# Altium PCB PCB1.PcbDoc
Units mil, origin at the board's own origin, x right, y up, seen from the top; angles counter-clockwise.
Board outline 6000 x 4000 mil, 2 copper layers (Top Layer, Bottom Layer); 0 components, 0 nets, 0 pads, 0 vias.
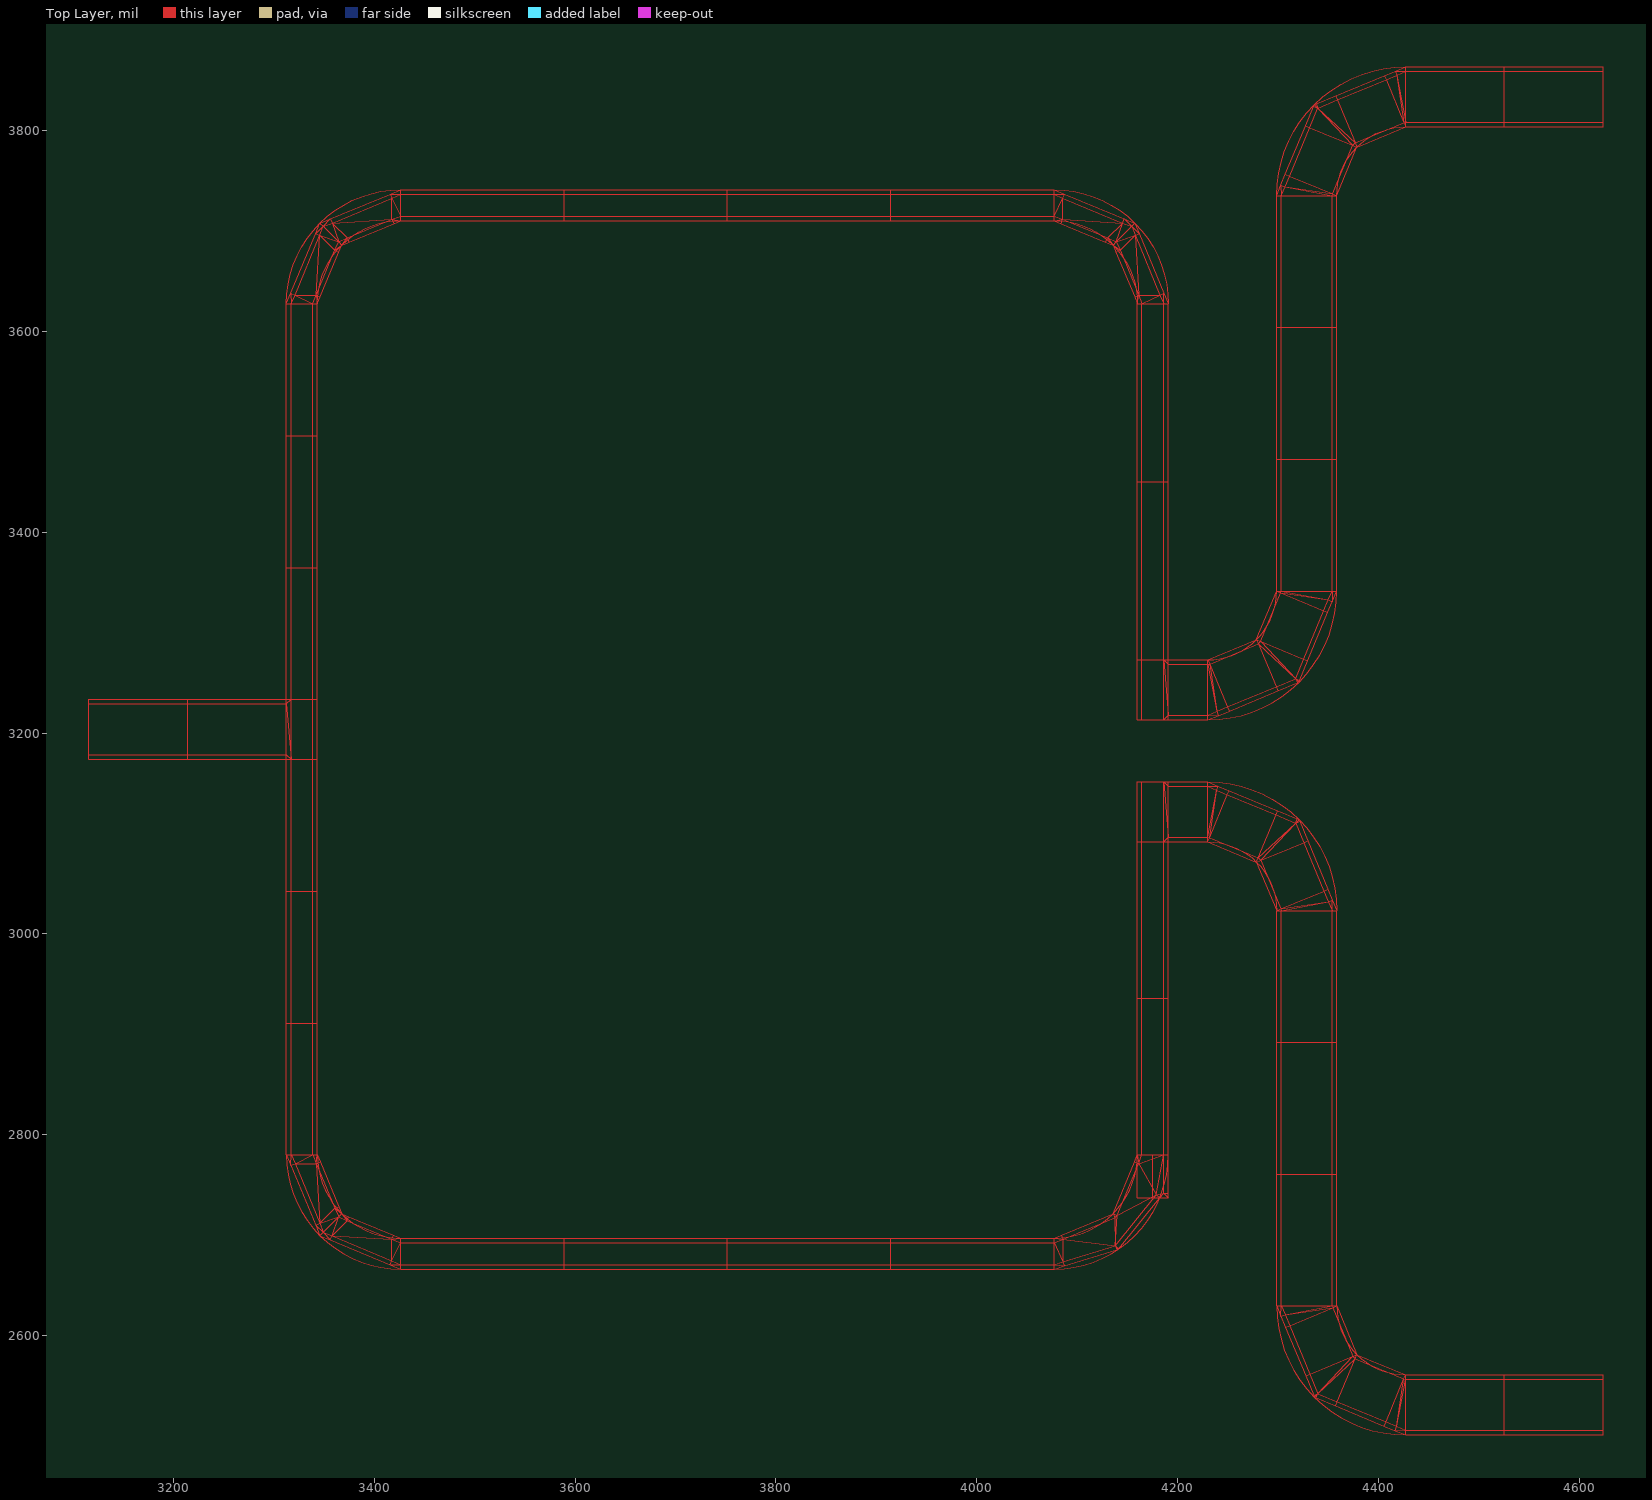
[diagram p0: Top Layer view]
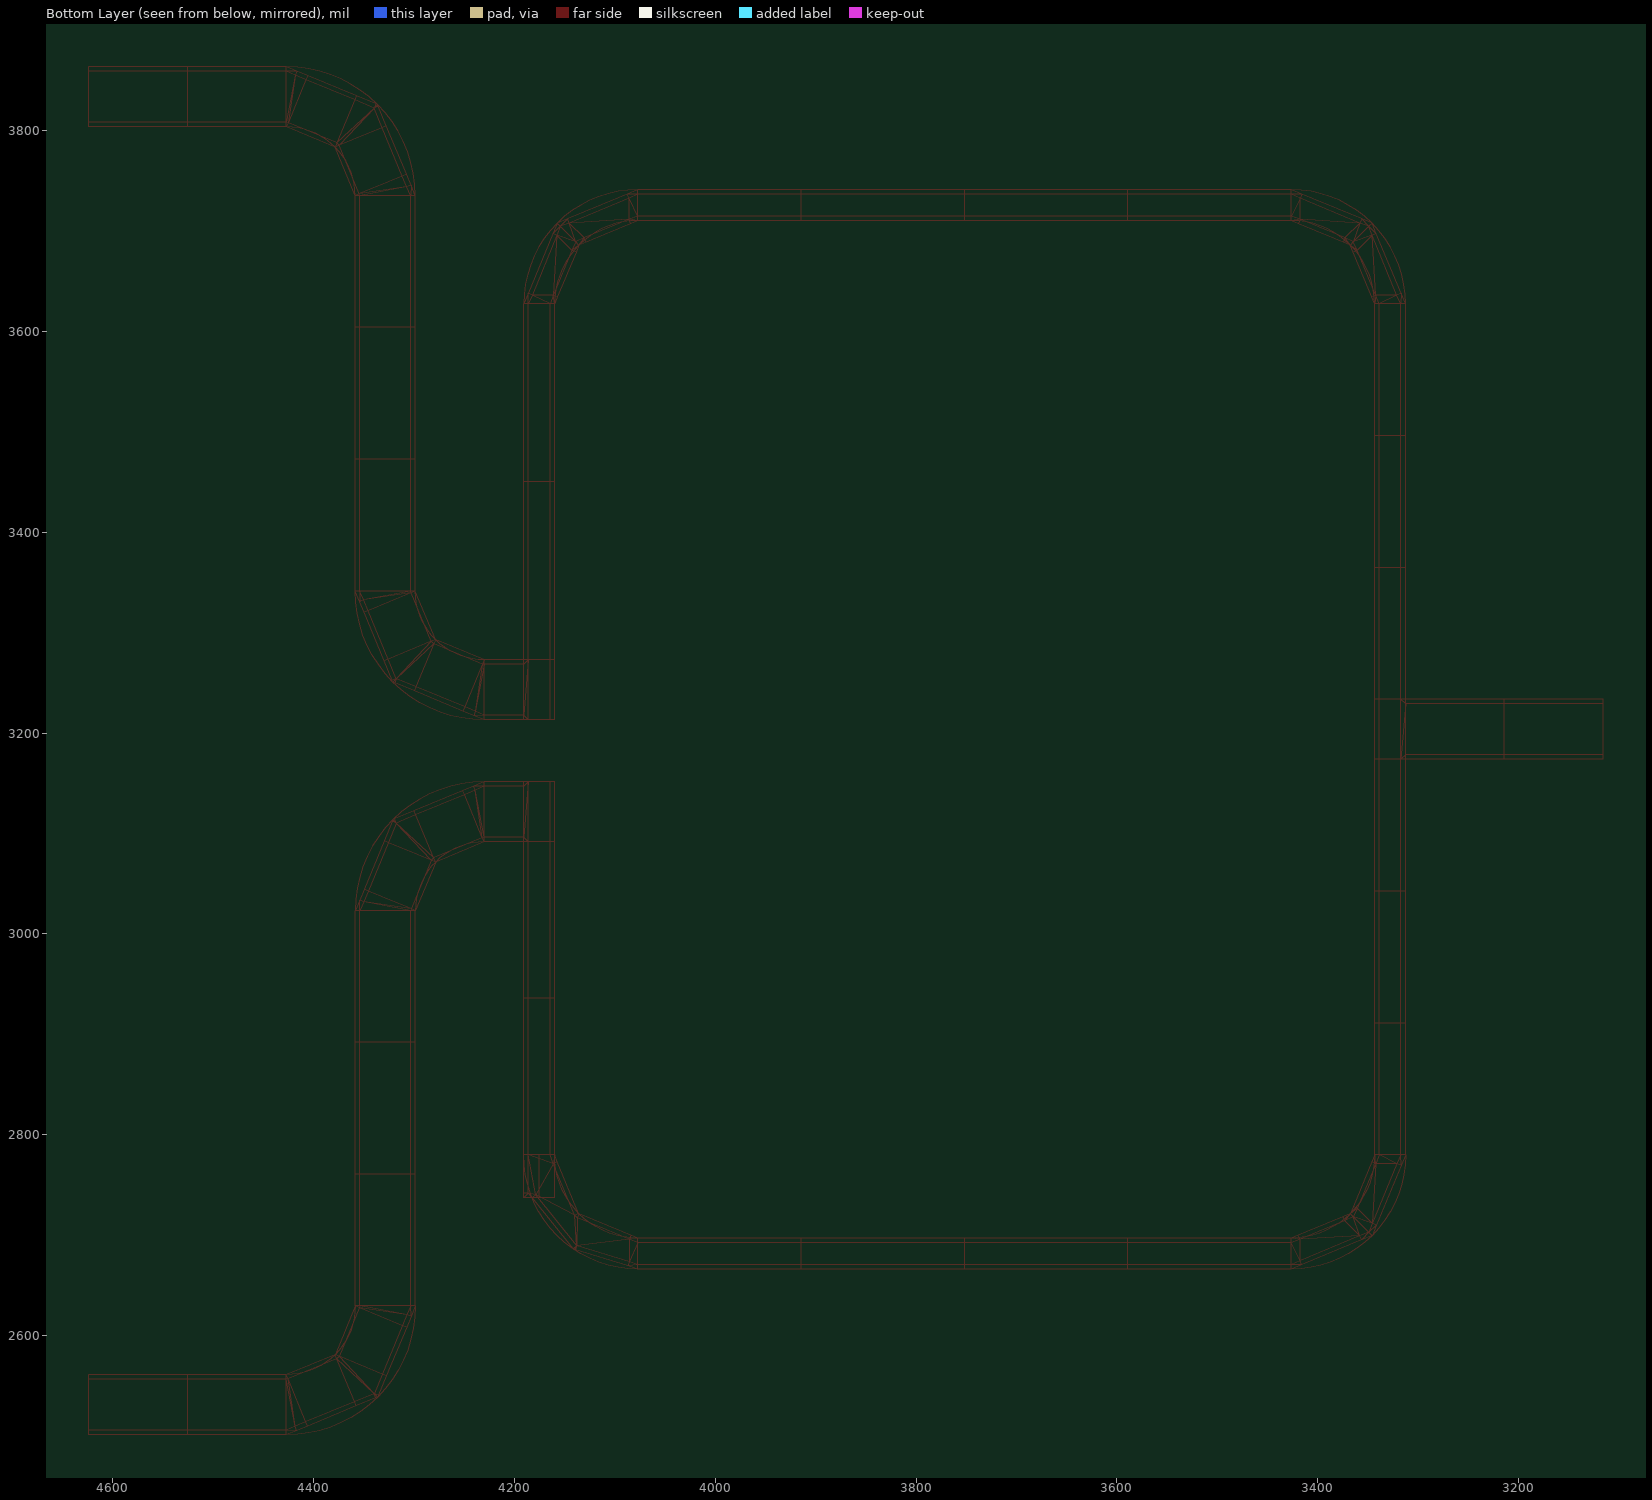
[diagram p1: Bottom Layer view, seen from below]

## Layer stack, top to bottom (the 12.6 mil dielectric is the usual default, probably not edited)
Top Layer: signal copper 1.4
Dielectric: dielectric 12.6, FR-4, Dk 4.8
Bottom Layer: signal copper 1.4

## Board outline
1000,1000 7000,1000 7000,5000 1000,5000

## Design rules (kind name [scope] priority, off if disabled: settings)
Clearance [All] p1: gap=10
ComponentClearance [All] p1: gap=10 collisioncheckmode=3 verticalgap=10
PolygonConnect [All] p1: connectstyle=Relief reliefconductorwidth=10 reliefentries=4 polygonreliefangle="90 Angle"
RoutingVias [All] p1: holewidth=28 width=50 viastyle="Through Hole" minholewidth=28 minwidth=50 maxholewidth=28 maxwidth=50
SolderMaskExpansion [All] p1: expansion=4
TestPointUsage [All] p1: valid=0 allowmultiple=FALSE
Testpoint [All] p1: side=15 testpointundercomponent=TRUE minsize=40 maxsize=100 preferedsize=60 minholesize=0 maxholesize=40 preferedholesize=32 testpointgrid=1 style=1023 order=0123456789
Width [All] p1: maxlimit=10 minlimit=10 preferedwidth=10
18 further rules are at their usual default settings.

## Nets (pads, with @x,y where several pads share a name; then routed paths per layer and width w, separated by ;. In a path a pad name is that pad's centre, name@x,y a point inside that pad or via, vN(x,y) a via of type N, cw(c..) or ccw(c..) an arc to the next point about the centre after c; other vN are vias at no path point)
copper on no net: | length 41882.3
  Top Layer w0.98: 4175.39,2737.3 4175.39,2780.03 ; 3115.69,3173.73 3312.54,3173.73 ; 3115.69,3173.73 3115.69,3233.62 ; 3115.69,3173.73 3115.69,3178.26 ; 3115.69,3173.73 3214.11,3173.73 ; 3115.69,3178.26 3214.11,3178.26 ; 3115.69,3178.26 3115.69,3229.09 ; 3115.69,3229.09 3115.69,3233.62 ; 3115.69,3229.09 3214.11,3229.09 ; 3115.69,3233.62 3312.54,3233.62 ; 3115.69,3233.62 3214.11,3233.62 ; 3214.11,3173.73 3214.11,3178.26 ; 3214.11,3173.73 3312.54,3173.73 ; 3214.11,3178.26 3312.54,3178.26 ; 3214.11,3178.26 3214.11,3229.09 ; 3214.11,3229.09 3214.11,3233.62 ; 3214.11,3229.09 3312.54,3229.09 ; 3214.11,3233.62 3312.54,3233.62 ; 3312.54,2780.03 3343.33,2780.03 ; 3312.54,2780.03 3312.54,3173.73 ; 3312.54,2780.03 3312.98,2770.11 3314.27,2760.26 3316.42,2750.57 3319.41,2741.1 3323.2,2731.93 3327.79,2723.12 3333.13,2714.74 3339.17,2706.87 3345.88,2699.55 ; 3312.54,2780.03 3343.33,2780.03 ; 3312.54,2780.03 3312.54,2911.26 ; 3312.54,2780.03 3317.07,2780.03 ; 3312.54,2780.03 3316.87,2769.57 ; 3312.54,2911.26 3312.54,3042.5 ; 3312.54,2911.26 3317.07,2911.26 ; 3312.54,3042.5 3312.54,3173.73 ; 3312.54,3042.5 3317.07,3042.5 ; 3312.54,3173.73 3312.54,3233.62 ; 3312.54,3173.73 3312.54,3233.62 ; 3312.54,3173.73 3343.33,3173.73 ; 3312.54,3173.73 3343.33,3173.73 ; 3312.54,3173.73 3317.07,3173.73 ; 3312.54,3173.73 3312.54,3178.26 ; 3312.54,3178.26 3312.54,3229.09 ; 3312.54,3178.26 3317.07,3173.73 ; 3312.54,3229.09 3312.54,3233.62 ; 3312.54,3229.09 3317.07,3233.62 ; 3312.54,3229.09 3317.07,3173.73 ; 3312.54,3233.62 3343.33,3233.62 ; 3312.54,3233.62 3312.54,3627.32 ; 3312.54,3233.62 3343.33,3233.62 ; 3312.54,3233.62 3312.54,3364.85 ; 3312.54,3233.62 3317.07,3233.62 ; 3312.54,3364.85 3312.54,3496.09 ; 3312.54,3364.85 3317.07,3364.85 ; 3312.54,3496.09 3312.54,3627.32 ; 3312.54,3496.09 3317.07,3496.09 ; 3312.54,3627.32 3343.33,3627.32 ; 3312.54,3627.32 3312.98,3637.24 3314.27,3647.09 3316.42,3656.78 3319.41,3666.25 3323.2,3675.43 3327.79,3684.23 3333.13,3692.61 3339.17,3700.48 3345.88,3707.81 3353.2,3714.52 3361.07,3720.56 3369.45,3725.89 3378.26,3730.48 3387.43,3734.28 3396.9,3737.26 3406.59,3739.41 3416.44,3740.7 3426.36,3741.14 ; 3312.54,3627.32 3343.33,3627.32 ; 3312.54,3627.32 3317.07,3627.32 ; 3312.54,3627.32 3316.87,3637.78 ; 3316.87,2769.57 3341.54,2710 ; 3316.87,2769.57 3321.06,2771.3 ; 3316.87,2769.57 3317.07,2780.03 ; 3316.87,3637.78 3321.06,3636.05 ; 3316.87,3637.78 3341.54,3697.35 ; 3316.87,3637.78 3317.07,3627.32 ; 3317.07,2780.03 3317.07,2911.26 ; 3317.07,2780.03 3338.79,2780.03 ; 3317.07,2780.03 3321.06,2771.3 ; 3317.07,2911.26 3317.07,3042.5 ; 3317.07,2911.26 3338.79,2911.26 ; 3317.07,3042.5 3317.07,3173.73 ; 3317.07,3042.5 3338.79,3042.5 ; 3317.07,3173.73 3338.79,3173.73 ; 3317.07,3173.73 3317.07,3233.62 ; 3317.07,3233.62 3317.07,3364.85 ; 3317.07,3233.62 3338.79,3233.62 ; 3317.07,3364.85 3317.07,3496.09 ; 3317.07,3364.85 3338.79,3364.85 ; 3317.07,3496.09 3317.07,3627.32 ; 3317.07,3496.09 3338.79,3496.09 ; 3317.07,3627.32 3338.79,3627.32 ; 3317.07,3627.32 3321.06,3636.05 ; 3321.06,2771.3 3345.73,2711.74 ; 3321.06,2771.3 3338.79,2780.03 ; 3321.06,2771.3 3342.03,2771.3 ; 3321.06,3636.05 3345.73,3695.61 ; 3321.06,3636.05 3338.79,3627.32 ; 3321.06,3636.05 3342.03,3636.05 ; 3338.79,2780.03 3338.79,2911.26 ; 3338.79,2780.03 3343.33,2780.03 ; 3338.79,2780.03 3342.03,2771.3 ; 3338.79,2911.26 3338.79,3042.5 ; 3338.79,2911.26 3343.33,2911.26 ; 3338.79,3042.5 3338.79,3173.73 ; 3338.79,3042.5 3343.33,3042.5 ; 3338.79,3173.73 3343.33,3173.73 ; 3338.79,3173.73 3338.79,3233.62 ; 3338.79,3233.62 3338.79,3364.85 ; 3338.79,3233.62 3343.33,3233.62 ; 3338.79,3364.85 3338.79,3496.09 ; 3338.79,3364.85 3343.33,3364.85 ; 3338.79,3496.09 3338.79,3627.32 ; 3338.79,3496.09 3343.33,3496.09 ; 3338.79,3627.32 3343.33,3627.32 ; 3338.79,3627.32 3342.03,3636.05 ; 3341.54,2710 3345.73,2711.74 ; 3341.54,2710 3349.08,2702.75 ; 3341.54,2710 3345.88,2699.55 ; 3341.54,3697.35 3345.73,3695.61 ; 3341.54,3697.35 3349.08,3704.6 ; 3341.54,3697.35 3345.87,3707.81 ; 3342.03,2771.3 3360.56,2726.57 ; 3342.03,2771.3 3346.22,2773.04 ; 3342.03,2771.3 3343.33,2780.03 ; 3342.03,2771.3 3345.73,2711.74 ; 3342.03,3636.05 3346.22,3634.31 ; 3342.03,3636.05 3360.56,3680.78 ; 3342.03,3636.05 3343.33,3627.32 ; 3342.03,3636.05 3345.73,3695.61 ; 3343.33,2780.03 3343.33,3173.73 ; 3343.33,2780.03 3343.65,2772.79 3344.59,2765.61 3346.16,2758.54 3348.33,2751.63 3351.11,2744.94 3354.45,2738.51 3358.35,2732.41 3362.76,2726.66 3367.65,2721.32 ; 3343.33,2780.03 3343.33,2911.26 ; 3343.33,2780.03 3346.22,2773.04 ; 3343.33,2911.26 3343.33,3042.5 ; 3343.33,3042.5 3343.33,3173.73 ; 3343.33,3173.73 3343.33,3233.62 ; 3343.33,3173.73 3343.33,3233.62 ; 3343.33,3233.62 3343.33,3627.32 ; 3343.33,3233.62 3343.33,3364.85 ; 3343.33,3364.85 3343.33,3496.09 ; 3343.33,3496.09 3343.33,3627.32 ; 3343.33,3627.32 3343.65,3634.56 3344.59,3641.74 3346.16,3648.82 3348.33,3655.72 3351.11,3662.42 3354.45,3668.84 3358.35,3674.95 3362.76,3680.7 3367.65,3686.04 ; 3343.33,3627.32 3346.22,3634.31 ; 3345.73,2711.74 3360.56,2726.57 ; 3345.73,2711.74 3364.44,2718.11 ; 3345.73,2711.74 3349.08,2702.75 ; 3345.73,3695.61 3360.56,3680.78 ; 3345.73,3695.61 3349.08,3704.6 ; 3345.73,3695.61 3364.44,3689.24 ; 3345.87,3707.81 3349.08,3704.6 ; 3345.87,3707.81 3356.33,3712.14 ; 3345.88,2699.55 3353.2,2692.84 3361.07,2686.8 3369.45,2681.46 3378.26,2676.87 3387.43,2673.07 3396.9,2670.09 3406.59,2667.94 3416.44,2666.65 3426.36,2666.21 ; 3345.88,2699.55 3349.08,2702.75 ; 3345.88,2699.55 3356.33,2695.21 ; 3346.22,2773.04 3364.75,2728.31 ; 3346.22,3634.31 3364.75,3679.05 ; 3349.08,2702.75 3364.44,2718.11 ; 3349.08,2702.75 3358.07,2699.4 ; 3349.08,2702.75 3356.33,2695.21 ; 3349.08,3704.6 3364.44,3689.24 ; 3349.08,3704.6 3358.07,3707.95 ; 3349.08,3704.6 3356.33,3712.14 ; 3356.33,2695.21 3415.9,2670.54 ; 3356.33,2695.21 3358.07,2699.4 ; 3356.33,3712.14 3358.07,3707.95 ; 3356.33,3712.14 3415.9,3736.81 ; 3358.07,2699.4 3417.63,2674.73 ; 3358.07,2699.4 3417.63,2695.7 ; 3358.07,2699.4 3372.9,2714.23 ; 3358.07,2699.4 3364.44,2718.11 ; 3358.07,3707.95 3417.63,3732.62 ; 3358.07,3707.95 3417.63,3711.65 ; 3358.07,3707.95 3372.9,3693.12 ; 3358.07,3707.95 3364.44,3689.24 ; 3360.56,2726.57 3364.75,2728.31 ; 3360.56,2726.57 3367.65,2721.32 ; 3360.56,2726.57 3364.44,2718.11 ; 3360.56,3680.78 3364.75,3679.05 ; 3360.56,3680.78 3364.44,3689.24 ; 3360.56,3680.78 3367.65,3686.04 ; 3364.44,2718.11 3367.65,2721.32 ; 3364.44,2718.11 3372.9,2714.23 ; 3364.44,3689.24 3367.65,3686.04 ; 3364.44,3689.24 3372.9,3693.12 ; 3364.75,2728.31 3367.65,2721.32 ; 3364.75,3679.05 3367.65,3686.04 ; 3367.65,2721.32 3372.99,2716.43 3378.74,2712.02 3384.84,2708.12 3391.27,2704.78 3397.96,2702 3404.87,2699.83 3411.94,2698.26 3419.12,2697.32 3426.36,2697 ; 3367.65,2721.32 3372.9,2714.23 ; 3367.65,2721.32 3374.64,2718.42 ; 3367.65,3686.04 3372.99,3690.93 3378.74,3695.34 3384.84,3699.23 3391.27,3702.58 3397.96,3705.35 3404.87,3707.53 3411.94,3709.09 3419.12,3710.04 3426.36,3710.35 ; 3367.65,3686.04 3372.9,3693.12 ; 3367.65,3686.04 3374.63,3688.93 ; 3372.9,2714.23 3417.63,2695.7 ; 3372.9,2714.23 3374.64,2718.42 ; 3372.9,3693.12 3374.63,3688.93 ; 3372.9,3693.12 3417.63,3711.65 ; 3374.64,2718.42 3419.37,2699.89 ; 3374.63,3688.93 3419.37,3707.46 ; 3415.9,2670.54 3417.63,2674.73 ; 3415.9,2670.54 3426.36,2670.74 ; 3415.9,2670.54 3426.36,2666.21 ; 3415.9,3736.81 3417.63,3732.62 ; 3415.9,3736.81 3426.36,3741.14 ; 3415.9,3736.81 3426.36,3736.61 ; 3417.63,2674.73 3426.36,2692.46 ; 3417.63,2674.73 3417.63,2695.7 ; 3417.63,2674.73 3426.36,2670.74 ; 3417.63,2695.7 3419.37,2699.89 ; 3417.63,2695.7 3426.36,2697 ; 3417.63,2695.7 3426.36,2692.46 ; 3417.63,3711.65 3419.37,3707.46 ; 3417.63,3711.65 3426.36,3714.89 ; 3417.63,3711.65 3426.36,3710.35 ; 3417.63,3711.65 3417.63,3732.62 ; 3417.63,3732.62 3426.36,3736.61 ; 3417.63,3732.62 3426.36,3714.89 ; 3419.37,2699.89 3426.36,2697 ; 3419.37,3707.46 3426.36,3710.35 ; 3426.36,2666.21 3426.36,2697 ; 3426.36,2666.21 4076.97,2666.21 ; 3426.36,2666.21 3426.36,2697 ; 3426.36,2666.21 3426.36,2670.74 ; 3426.36,2666.21 3589.01,2666.21 ; 3426.36,2670.74 3589.01,2670.74 ; 3426.36,2670.74 3426.36,2692.46 ; 3426.36,2692.46 3426.36,2697 ; 3426.36,2692.46 3589.01,2692.46 ; 3426.36,2697 4076.97,2697 ; 3426.36,2697 3589.01,2697 ; 3426.36,3710.35 4076.97,3710.35 ; 3426.36,3710.35 3426.36,3741.14 ; 3426.36,3710.35 3426.36,3741.14 ; 3426.36,3710.35 3426.36,3714.89 ; 3426.36,3710.35 3589.01,3710.35 ; 3426.36,3714.89 3589.01,3714.89 ; 3426.36,3714.89 3426.36,3736.61 ; 3426.36,3736.61 3426.36,3741.14 ; 3426.36,3736.61 3589.01,3736.61 ; 3426.36,3741.14 4076.97,3741.14 ; 3426.36,3741.14 3589.01,3741.14 ; 3589.01,2666.21 3589.01,2670.74 ; 3589.01,2666.21 3751.67,2666.21 ; 3589.01,2670.74 3751.67,2670.74 ; 3589.01,2670.74 3589.01,2692.46 ; 3589.01,2692.46 3589.01,2697 ; 3589.01,2692.46 3751.67,2692.46 ; 3589.01,2697 3751.67,2697 ; 3589.01,3710.35 3589.01,3714.89 ; 3589.01,3710.35 3751.67,3710.35 ; 3589.01,3714.89 3751.67,3714.89 ; 3589.01,3714.89 3589.01,3736.61 ; 3589.01,3736.61 3589.01,3741.14 ; 3589.01,3736.61 3751.67,3736.61 ; 3589.01,3741.14 3751.67,3741.14 ; 3751.67,2666.21 3751.67,2670.74 ; 3751.67,2666.21 3914.31,2666.21 ; 3751.67,2670.74 3914.31,2670.74 ; 3751.67,2670.74 3751.67,2692.46 ; 3751.67,2692.46 3751.67,2697 ; 3751.67,2692.46 3914.31,2692.46 ; 3751.67,2697 3914.31,2697 ; 3751.67,3710.35 3751.67,3714.89 ; 3751.67,3710.35 3914.31,3710.35 ; 3751.67,3714.89 3914.31,3714.89 ; 3751.67,3714.89 3751.67,3736.61 ; 3751.67,3736.61 3751.67,3741.14 ; 3751.67,3736.61 3914.31,3736.61 ; 3751.67,3741.14 3914.31,3741.14 ; 3914.31,2666.21 3914.31,2670.74 ; 3914.31,2666.21 4076.97,2666.21 ; 3914.31,2670.74 4076.97,2670.74 ; 3914.31,2670.74 3914.31,2692.46 ; 3914.31,2692.46 3914.31,2697 ; 3914.31,2692.46 4076.97,2692.46 ; 3914.31,2697 4076.97,2697 ; 3914.31,3710.35 3914.31,3714.89 ; 3914.31,3710.35 4076.97,3710.35 ; 3914.31,3714.89 4076.97,3714.89 ; 3914.31,3714.89 3914.31,3736.61 ; 3914.31,3736.61 3914.31,3741.14 ; 3914.31,3736.61 4076.97,3736.61 ; 3914.31,3741.14 4076.97,3741.14 ; 4076.97,2666.21 4076.97,2697 ; 4076.97,2666.21 4086.89,2666.65 4096.73,2667.94 4106.43,2670.09 4115.89,2673.07 4125.07,2676.87 4133.87,2681.46 4142.25,2686.8 4150.13,2692.84 4157.45,2699.55 4164.16,2706.87 4170.2,2714.74 4175.54,2723.12 4180.12,2731.93 4183.92,2741.1 4186.91,2750.57 4189.06,2760.26 4190.35,2770.11 4190.79,2780.03 ; 4076.97,2666.21 4076.97,2697 ; 4076.97,2666.21 4076.97,2670.74 ; 4076.97,2666.21 4087.17,2669.32 ; 4076.97,2670.74 4076.97,2692.46 ; 4076.97,2670.74 4085.84,2673.66 ; 4076.97,2670.74 4087.17,2669.32 ; 4076.97,2692.46 4076.97,2697 ; 4076.97,2692.46 4085.84,2673.66 ; 4076.97,2692.46 4085.69,2695.7 ; 4076.97,2697 4084.2,2697.32 4091.39,2698.26 4098.46,2699.83 4105.37,2702 4112.06,2704.78 4118.48,2708.12 4124.59,2712.02 4130.34,2716.43 4135.68,2721.32 ; 4076.97,2697 4085.69,2695.7 ; 4076.97,2697 4083.96,2699.89 ; 4076.97,3710.35 4084.2,3710.04 4091.39,3709.09 4098.46,3707.53 4105.37,3705.35 4112.06,3702.58 4118.48,3699.23 4124.59,3695.34 4130.34,3690.93 4135.68,3686.04 ; 4076.97,3710.35 4076.97,3741.14 ; 4076.97,3710.35 4076.97,3741.14 ; 4076.97,3710.35 4076.97,3714.89 ; 4076.97,3710.35 4085.69,3711.65 ; 4076.97,3710.35 4083.96,3707.46 ; 4076.97,3714.89 4076.97,3736.61 ; 4076.97,3714.89 4085.69,3711.65 ; 4076.97,3714.89 4085.69,3732.62 ; 4076.97,3736.61 4076.97,3741.14 ; 4076.97,3736.61 4085.69,3732.62 ; 4076.97,3736.61 4087.43,3736.81 ; 4076.97,3741.14 4086.89,3740.7 4096.73,3739.41 4106.43,3737.26 4115.89,3734.28 4125.07,3730.48 4133.87,3725.89 4142.25,3720.56 4150.13,3714.52 4157.45,3707.81 ; 4076.97,3741.14 4087.43,3736.81 ; 4083.96,2699.89 4085.69,2695.7 ; 4083.96,2699.89 4135.68,2721.32 ; 4083.96,3707.46 4128.69,3688.93 ; 4083.96,3707.46 4085.69,3711.65 ; 4085.69,2695.7 4137.41,2717.13 ; 4085.69,2695.7 4085.84,2673.66 ; 4085.69,2695.7 4137.9,2689.56 ; 4085.69,3711.65 4130.43,3693.12 ; 4085.69,3711.65 4085.69,3732.62 ; 4085.69,3711.65 4145.26,3707.95 ; 4085.69,3732.62 4145.26,3707.95 ; 4085.69,3732.62 4087.43,3736.81 ; 4085.84,2673.66 4087.17,2669.32 ; 4085.84,2673.66 4137.9,2689.56 ; 4087.17,2669.32 4139.23,2685.22 ; 4087.43,3736.81 4147,3712.14 ; 4128.69,3688.93 4130.43,3693.12 ; 4128.69,3688.93 4135.68,3686.04 ; 4130.43,3693.12 4145.26,3707.95 ; 4130.43,3693.12 4138.89,3689.24 ; 4130.43,3693.12 4135.68,3686.04 ; 4135.68,2721.32 4140.57,2726.66 4144.98,2732.41 4148.87,2738.52 4152.22,2744.94 4154.99,2751.63 4157.17,2758.54 4158.74,2765.61 4159.68,2772.79 4160,2780.03 ; 4135.68,2721.32 4137.41,2717.13 ; 4135.68,2721.32 4139.87,2719.58 ; 4135.68,2721.32 4157.11,2773.04 ; 4135.68,3686.04 4140.57,3680.7 4144.98,3674.95 4148.87,3668.84 4152.22,3662.42 4154.99,3655.72 4157.17,3648.82 4158.74,3641.74 4159.68,3634.56 4160,3627.32 ; 4135.68,3686.04 4138.89,3689.24 ; 4135.68,3686.04 4142.76,3680.78 ; 4135.68,3686.04 4138.57,3679.05 ; 4137.41,2717.13 4137.9,2689.56 ; 4137.41,2717.13 4139.87,2719.58 ; 4137.9,2689.56 4141.43,2686.7 ; 4137.9,2689.56 4178.82,2740.15 ; 4137.9,2689.56 4139.23,2685.22 ; 4137.9,2689.56 4140.56,2685.63 ; 4137.9,2689.56 4139.87,2719.58 ; 4138.57,3679.05 4157.11,3634.31 ; 4138.57,3679.05 4142.76,3680.78 ; 4138.89,3689.24 4145.26,3707.95 ; 4138.89,3689.24 4154.25,3704.6 ; 4138.89,3689.24 4142.76,3680.78 ; 4138.89,3689.24 4157.6,3695.61 ; 4139.23,2685.22 4140.56,2685.63 ; 4139.87,2719.58 4161.3,2771.3 ; 4139.87,2719.58 4178.82,2740.15 ; 4140.56,2685.63 4141.43,2686.7 ; 4141.43,2686.7 4182.35,2737.3 ; 4142.76,3680.78 4161.3,3636.05 ; 4142.76,3680.78 4157.6,3695.61 ; 4145.26,3707.95 4147,3712.14 ; 4145.26,3707.95 4154.25,3704.6 ; 4147,3712.14 4154.25,3704.6 ; 4147,3712.14 4157.46,3707.81 ; 4154.25,3704.6 4157.46,3707.81 ; 4154.25,3704.6 4157.6,3695.61 ; 4154.25,3704.6 4161.79,3697.35 ; 4157.11,2773.04 4161.3,2771.3 ; 4157.11,2773.04 4160,2780.03 ; 4157.11,3634.31 4161.3,3636.05 ; 4157.11,3634.31 4160,3627.32 ; 4157.45,3707.81 4164.16,3700.48 4170.2,3692.61 4175.54,3684.23 4180.12,3675.43 4183.92,3666.25 4186.91,3656.78 4189.06,3647.09 4190.35,3637.24 4190.79,3627.32 ; 4157.46,3707.81 4161.79,3697.35 ; 4157.6,3695.61 4182.27,3636.05 ; 4157.6,3695.61 4161.79,3697.35 ; 4157.6,3695.61 4161.3,3636.05 ; 4160,2780.03 4190.79,2780.03 ; 4160,2780.03 4160,2935.83 ; 4160,2780.03 4164.54,2780.03 ; 4160,2780.03 4161.3,2771.3 ; 4160,2935.83 4160,3091.63 ; 4160,2935.83 4164.54,2935.83 ; 4160,3091.63 4160,2737.3 4190.79,2737.3 ; 4160,3091.63 4190.79,3091.63 ; 4160,3091.63 4160,3151.52 ; 4160,3091.63 4190.79,3091.63 ; 4160,3091.63 4164.54,3091.63 ; 4160,3091.63 4160,3151.52 ; 4160,3151.52 4190.79,3151.52 ; 4160,3151.52 4164.54,3151.52 ; 4160,3213.1 4160,3272.99 ; 4160,3213.1 4190.79,3213.1 ; 4160,3213.1 4160,3272.99 ; 4160,3213.1 4164.54,3213.1 ; 4160,3272.99 4190.79,3272.99 ; 4160,3272.99 4190.79,3272.99 ; 4160,3272.99 4160,3627.32 ; 4160,3272.99 4160,3450.16 ; 4160,3272.99 4164.54,3272.99 ; 4160,3450.16 4160,3627.32 ; 4160,3450.16 4164.54,3450.16 ; 4160,3627.32 4190.79,3627.32 ; 4160,3627.32 4190.79,3627.32 ; 4160,3627.32 4164.54,3627.32 ; 4160,3627.32 4161.3,3636.05 ; 4161.3,2771.3 4164.54,2780.03 ; 4161.3,2771.3 4178.82,2740.15 ; 4161.3,2771.3 4186.25,2780.03 ; 4161.3,3636.05 4164.54,3627.32 ; 4161.3,3636.05 4182.27,3636.05 ; 4161.79,3697.35 4186.46,3637.78 ; 4164.54,2780.03 4164.54,2935.83 ; 4164.54,2780.03 4186.25,2780.03 ; 4164.54,2935.83 4164.54,3091.63 ; 4164.54,2935.83 4186.25,2935.83 ; 4164.54,3091.63 4164.54,3151.52 ; 4164.54,3091.63 4186.25,3091.63 ; 4164.54,3151.52 4186.25,3151.52 ; 4164.54,3213.1 4164.54,3272.99 ; 4164.54,3213.1 4186.25,3213.1 ; 4164.54,3272.99 4164.54,3450.16 ; 4164.54,3272.99 4186.25,3272.99 ; 4164.54,3450.16 4164.54,3627.32 ; 4164.54,3450.16 4186.25,3450.16 ; 4164.54,3627.32 4186.25,3627.32 ; 4164.54,3627.32 4182.27,3636.05 ; 4178.82,2740.15 4182.35,2737.3 ; 4178.82,2740.15 4186.25,2780.03 ; 4178.82,2740.15 4186.25,2741.83 ; 4182.27,3636.05 4186.46,3637.78 ; 4182.27,3636.05 4186.25,3627.32 ; 4182.35,2737.3 4186.25,2741.83 ; 4182.35,2737.3 4190.79,2737.3 ; 4186.25,2741.83 4186.25,2780.03 ; 4186.25,2741.83 4190.79,2741.83 ; 4186.25,2741.83 4190.79,2737.3 ; 4186.25,2780.03 4186.25,2935.83 ; 4186.25,2780.03 4190.79,2780.03 ; 4186.25,2935.83 4186.25,3091.63 ; 4186.25,2935.83 4190.79,2935.83 ; 4186.25,3091.63 4190.79,3091.63 ; 4186.25,3091.63 4186.25,3151.52 ; 4186.25,3091.63 4190.79,3096.16 ; 4186.25,3151.52 4190.79,3096.16 ; 4186.25,3151.52 4190.79,3146.98 ; 4186.25,3151.52 4190.79,3151.52 ; 4186.25,3213.1 4186.25,3272.99 ; 4186.25,3213.1 4190.79,3217.63 ; 4186.25,3213.1 4190.79,3213.1 ; 4186.25,3272.99 4186.25,3450.16 ; 4186.25,3272.99 4190.79,3272.99 ; 4186.25,3272.99 4190.79,3217.63 ; 4186.25,3272.99 4190.79,3268.46 ; 4186.25,3450.16 4186.25,3627.32 ; 4186.25,3450.16 4190.79,3450.16 ; 4186.25,3627.32 4190.79,3627.32 ; 4186.25,3627.32 4186.46,3637.78 ; 4186.46,3637.78 4190.79,3627.32 ; 4190.79,2737.3 4190.79,3091.63 ; 4190.79,2737.3 4190.79,2741.83 ; 4190.79,2741.83 4190.79,2780.03 ; 4190.79,2780.03 4190.79,2935.83 ; 4190.79,2935.83 4190.79,3091.63 ; 4190.79,3091.63 4190.79,3151.52 ; 4190.79,3091.63 4230.16,3091.63 ; 4190.79,3091.63 4190.79,3151.52 ; 4190.79,3091.63 4190.79,3096.16 ; 4190.79,3091.63 4230.16,3091.63 ; 4190.79,3096.16 4230.16,3096.16 ; 4190.79,3096.16 4190.79,3146.98 ; 4190.79,3146.98 4190.79,3151.52 ; 4190.79,3146.98 4230.16,3146.98 ; 4190.79,3151.52 4230.16,3151.52 ; 4190.79,3151.52 4230.16,3151.52 ; 4190.79,3213.1 4230.16,3213.1 ; 4190.79,3213.1 4190.79,3272.99 ; 4190.79,3213.1 4190.79,3272.99 ; 4190.79,3213.1 4190.79,3217.63 ; 4190.79,3213.1 4230.16,3213.1 ; 4190.79,3217.63 4230.16,3217.63 ; 4190.79,3217.63 4190.79,3268.46 ; 4190.79,3268.46 4190.79,3272.99 ; 4190.79,3268.46 4230.16,3268.46 ; 4190.79,3272.99 4230.16,3272.99 ; 4190.79,3272.99 4190.79,3627.32 ; 4190.79,3272.99 4190.79,3450.16 ; 4190.79,3272.99 4230.16,3272.99 ; 4190.79,3450.16 4190.79,3627.32 ; 4230.16,3091.63 4230.16,3151.52 ; 4230.16,3091.63 4236.12,3091.37 4242.05,3090.59 4247.88,3089.3 4253.57,3087.5 4259.09,3085.21 4264.39,3082.45 4269.43,3079.24 4274.17,3075.61 4278.58,3071.57 ; 4230.16,3091.63 4230.16,3151.52 ; 4230.16,3091.63 4278.58,3071.57 ; 4230.16,3091.63 4231.89,3095.82 ; 4230.16,3091.63 4230.16,3096.16 ; 4230.16,3096.16 4230.16,3146.98 ; 4230.16,3096.16 4231.89,3095.82 ; 4230.16,3096.16 4238.88,3143 ; 4230.16,3146.98 4230.16,3151.52 ; 4230.16,3146.98 4238.88,3143 ; 4230.16,3146.98 4240.61,3147.19 ; 4230.16,3151.52 4241.34,3151.04 4252.45,3149.57 4263.38,3147.15 4274.06,3143.78 4284.41,3139.5 4294.34,3134.33 4303.79,3128.31 4312.67,3121.49 4320.93,3113.93 ; 4230.16,3151.52 4240.61,3147.19 ; 4230.16,3213.1 4241.34,3213.59 4252.45,3215.05 4263.38,3217.48 4274.06,3220.84 4284.41,3225.13 4294.34,3230.3 4303.79,3236.32 4312.67,3243.13 4320.93,3250.7 ; 4230.16,3213.1 4230.16,3272.99 ; 4230.16,3213.1 4230.16,3272.99 ; 4230.16,3213.1 4230.16,3217.63 ; 4230.16,3213.1 4240.61,3217.43 ; 4230.16,3217.63 4230.16,3268.46 ; 4230.16,3217.63 4240.61,3217.43 ; 4230.16,3217.63 4238.88,3221.62 ; 4230.16,3268.46 4230.16,3272.99 ; 4230.16,3268.46 4238.88,3221.62 ; 4230.16,3268.46 4231.89,3268.8 ; 4230.16,3272.99 4236.12,3273.26 4242.05,3274.04 4247.88,3275.33 4253.57,3277.13 4259.09,3279.41 4264.39,3282.17 4269.43,3285.38 4274.17,3289.02 4278.57,3293.06 ; 4230.16,3272.99 4231.89,3268.8 ; 4230.16,3272.99 4278.57,3293.06 ; 4231.89,3095.82 4280.31,3075.76 ; 4231.89,3095.82 4249.6,3138.56 ; 4231.89,3095.82 4238.88,3143 ; 4231.89,3268.8 4280.31,3288.87 ; 4231.89,3268.8 4249.61,3226.06 ; 4231.89,3268.8 4238.88,3221.62 ; 4238.88,3143 4249.6,3138.56 ; 4238.88,3143 4240.61,3147.19 ; 4238.88,3221.62 4240.61,3217.43 ; 4238.88,3221.62 4249.61,3226.06 ; 4240.61,3147.19 4251.33,3142.75 ; 4240.61,3217.43 4251.34,3221.87 ; 4249.6,3138.56 4298.02,3118.51 ; 4249.6,3138.56 4251.33,3142.75 ; 4249.61,3226.06 4251.34,3221.87 ; 4249.61,3226.06 4298.02,3246.13 ; 4251.33,3142.75 4299.75,3122.7 ; 4251.34,3221.87 4299.76,3241.94 ; 4278.57,3293.06 4282.61,3297.46 4286.25,3302.2 4289.46,3307.24 4292.22,3312.54 4294.5,3318.06 4296.3,3323.75 4297.59,3329.58 4298.37,3335.51 4298.63,3341.47 ; 4278.57,3293.06 4282.76,3291.32 ; 4278.57,3293.06 4298.63,3341.47 ; 4278.57,3293.06 4280.31,3288.87 ; 4278.58,3071.57 4282.61,3067.17 4286.25,3062.43 4289.46,3057.39 4292.22,3052.09 4294.5,3046.57 4296.3,3040.87 4297.59,3035.04 4298.37,3029.12 4298.63,3023.15 ; 4278.58,3071.57 4298.63,3023.15 ; 4278.58,3071.57 4282.77,3073.3 ; 4278.58,3071.57 4280.31,3075.76 ; 4280.31,3075.76 4298.02,3118.51 ; 4280.31,3075.76 4282.77,3073.3 ; 4280.31,3075.76 4317.46,3110.45 ; 4280.31,3288.87 4298.02,3246.13 ; 4280.31,3288.87 4317.46,3254.17 ; 4280.31,3288.87 4282.76,3291.32 ; 4282.77,3073.3 4302.82,3024.89 ; 4282.77,3073.3 4325.52,3091.01 ; 4282.77,3073.3 4317.46,3110.45 ; 4282.76,3291.32 4302.82,3339.74 ; 4282.76,3291.32 4325.51,3273.61 ; 4282.76,3291.32 4317.46,3254.17 ; 4298.02,3118.51 4299.75,3122.7 ; 4298.02,3118.51 4317.46,3110.45 ; 4298.02,3246.13 4299.76,3241.94 ; 4298.02,3246.13 4317.46,3254.17 ; 4298.63,2629.45 4358.53,2629.45 ; 4298.63,2629.45 4298.63,3023.15 ; 4298.63,2629.45 4299.12,2618.26 4300.58,2607.16 4303.01,2596.22 4306.37,2585.54 4310.66,2575.2 4315.83,2565.26 4321.85,2555.82 4328.67,2546.93 4336.23,2538.67 ; 4298.63,2629.45 4358.53,2629.45 ; 4298.63,2629.45 4298.63,2760.68 ; 4298.63,2629.45 4303.17,2629.45 ; 4298.63,2629.45 4302.96,2618.99 ; 4298.63,2760.68 4298.63,2891.92 ; 4298.63,2760.68 4303.17,2760.68 ; 4298.63,2891.92 4298.63,3023.15 ; 4298.63,2891.92 4303.17,2891.92 ; 4298.63,3023.15 4358.53,3023.15 ; 4298.63,3023.15 4358.53,3023.15 ; 4298.63,3023.15 4303.17,3023.15 ; 4298.63,3023.15 4302.82,3024.89 ; 4298.63,3341.47 4358.53,3341.47 ; 4298.63,3341.47 4298.63,3735.17 ; 4298.63,3341.47 4358.53,3341.47 ; 4298.63,3341.47 4298.63,3472.7 ; 4298.63,3341.47 4303.17,3341.47 ; 4298.63,3341.47 4302.82,3339.74 ; 4298.63,3472.7 4298.63,3603.94 ; 4298.63,3472.7 4303.17,3472.7 ; 4298.63,3603.94 4298.63,3735.17 ; 4298.63,3603.94 4303.17,3603.94 ; 4298.63,3735.17 4358.53,3735.17 ; 4298.63,3735.17 4299.12,3746.36 4300.58,3757.46 4303.01,3768.4 4306.37,3779.08 4310.66,3789.43 4315.83,3799.36 4321.85,3808.8 4328.67,3817.69 4336.23,3825.95 ; 4298.63,3735.17 4358.53,3735.17 ; 4298.63,3735.17 4303.17,3735.17 ; 4298.63,3735.17 4302.96,3745.63 ; 4299.75,3122.7 4319.2,3114.64 ; 4299.76,3241.94 4319.19,3249.98 ; 4302.82,3024.89 4345.57,3042.59 ; 4302.82,3024.89 4303.17,3023.15 ; 4302.82,3024.89 4350.01,3031.87 ; 4302.82,3339.74 4345.57,3322.03 ; 4302.82,3339.74 4350.01,3332.75 ; 4302.82,3339.74 4303.17,3341.47 ; 4302.96,2618.99 4307.41,2608.27 ; 4302.96,2618.99 4307.15,2620.72 ; 4302.96,2618.99 4303.17,2629.45 ; 4302.96,3745.63 4307.15,3743.9 ; 4302.96,3745.63 4307.41,3756.35 ; 4302.96,3745.63 4303.17,3735.17 ; 4303.17,2629.45 4303.17,2760.68 ; 4303.17,2629.45 4354,2629.45 ; 4303.17,2629.45 4307.15,2620.72 ; 4303.17,2760.68 4303.17,2891.92 ; 4303.17,2760.68 4354,2760.68 ; 4303.17,2891.92 4303.17,3023.15 ; 4303.17,2891.92 4354,2891.92 ; 4303.17,3023.15 4354,3023.15 ; 4303.17,3023.15 4350.01,3031.87 ; 4303.17,3341.47 4303.17,3472.7 ; 4303.17,3341.47 4354,3341.47 ; 4303.17,3341.47 4350.01,3332.75 ; 4303.17,3472.7 4303.17,3603.94 ; 4303.17,3472.7 4354,3472.7 ; 4303.17,3603.94 4303.17,3735.17 ; 4303.17,3603.94 4354,3603.94 ; 4303.17,3735.17 4354,3735.17 ; 4303.17,3735.17 4307.15,3743.9 ; 4307.15,2620.72 4311.59,2610.01 ; 4307.15,2620.72 4354,2629.45 ; 4307.15,2620.72 4354.34,2627.71 ; 4307.15,3743.9 4311.59,3754.61 ; 4307.15,3743.9 4354.34,3736.91 ; 4307.15,3743.9 4354,3735.17 ; 4307.41,2608.27 4327.46,2559.85 ; 4307.41,2608.27 4311.59,2610.01 ; 4307.41,3756.35 4311.59,3754.61 ; 4307.41,3756.35 4327.46,3804.77 ; 4311.59,2610.01 4331.65,2561.59 ; 4311.59,2610.01 4354.34,2627.71 ; 4311.59,3754.61 4331.65,3803.04 ; 4311.59,3754.61 4354.34,3736.91 ; 4317.46,3110.45 4319.2,3114.64 ; 4317.46,3110.45 4325.52,3091.01 ; 4317.46,3110.45 4321.65,3112.19 ; 4317.46,3110.45 4320.93,3113.93 ; 4317.46,3254.17 4321.65,3252.44 ; 4317.46,3254.17 4325.51,3273.61 ; 4317.46,3254.17 4319.19,3249.98 ; 4317.46,3254.17 4320.93,3250.7 ; 4319.2,3114.64 4320.93,3113.93 ; 4319.19,3249.98 4320.93,3250.7 ; 4320.93,3113.93 4328.5,3105.67 4335.31,3096.78 4341.33,3087.34 4346.5,3077.41 4350.79,3067.06 4354.15,3056.38 4356.58,3045.44 4358.04,3034.34 4358.53,3023.15 ; 4320.93,3113.93 4321.65,3112.19 ; 4320.93,3250.7 4328.5,3258.96 4335.31,3267.84 4341.33,3277.29 4346.5,3287.22 4350.79,3297.57 4354.15,3308.25 4356.58,3319.18 4358.04,3330.29 4358.53,3341.47 ; 4320.93,3250.7 4321.65,3252.44 ; 4321.65,3112.19 4329.7,3092.75 ; 4321.65,3252.44 4329.7,3271.87 ; 4325.52,3091.01 4345.57,3042.59 ; 4325.52,3091.01 4329.7,3092.75 ; 4325.51,3273.61 4329.7,3271.87 ; 4325.51,3273.61 4345.57,3322.03 ; 4327.46,2559.85 4331.65,2561.59 ; 4327.46,2559.85 4335.52,2540.41 ; 4327.46,3804.77 4331.65,3803.04 ; 4327.46,3804.77 4335.52,3824.21 ; 4329.7,3092.75 4349.76,3044.33 ; 4329.7,3271.87 4349.76,3320.3 ; 4331.65,2561.59 4339.7,2542.15 ; 4331.65,2561.59 4374.4,2579.3 ; 4331.65,3803.04 4339.7,3822.48 ; 4331.65,3803.04 4374.4,3785.33 ; 4335.52,2540.41 4339.7,2542.15 ; 4335.52,2540.41 4336.23,2538.67 ; 4335.52,3824.21 4339.7,3822.48 ; 4335.52,3824.21 4336.23,3825.95 ; 4336.23,2538.67 4344.49,2531.11 4353.37,2524.29 4362.82,2518.28 4372.75,2513.11 4383.1,2508.82 4393.78,2505.45 4404.71,2503.03 4415.82,2501.57 4427.01,2501.07 ; 4336.23,2538.67 4337.97,2537.96 ; 4336.23,2538.67 4339.7,2542.15 ; 4336.23,3825.95 4344.49,3833.51 4353.37,3840.33 4362.82,3846.35 4372.75,3851.52 4383.1,3855.8 4393.78,3859.17 4404.71,3861.59 4415.82,3863.06 4427.01,3863.55 ; 4336.23,3825.95 4339.7,3822.48 ; 4336.23,3825.95 4337.97,3826.67 ; 4337.97,2537.96 4357.41,2529.9 ; 4337.97,2537.96 4339.7,2542.15 ; 4337.97,3826.67 4339.7,3822.48 ; 4337.97,3826.67 4357.41,3834.72 ; 4339.7,2542.15 4359.15,2534.09 ; 4339.7,2542.15 4374.4,2579.3 ; 4339.7,2542.15 4376.85,2576.84 ; 4339.7,3822.48 4359.15,3830.53 ; 4339.7,3822.48 4376.85,3787.78 ; 4339.7,3822.48 4374.4,3785.33 ; 4345.57,3042.59 4349.76,3044.33 ; 4345.57,3042.59 4350.01,3031.87 ; 4345.57,3322.03 4349.76,3320.3 ; 4345.57,3322.03 4350.01,3332.75 ; 4349.76,3044.33 4354.2,3033.61 ; 4349.76,3320.3 4354.2,3331.02 ; 4350.01,3031.87 4354.2,3033.61 ; 4350.01,3031.87 4354,3023.15 ; 4350.01,3332.75 4354.2,3331.02 ; 4350.01,3332.75 4354,3341.47 ; 4354,2629.45 4354,2760.68 ; 4354,2629.45 4358.53,2629.45 ; 4354,2629.45 4354.34,2627.71 ; 4354,2760.68 4354,2891.92 ; 4354,2760.68 4358.53,2760.68 ; 4354,2891.92 4354,3023.15 ; 4354,2891.92 4358.53,2891.92 ; 4354,3023.15 4358.53,3023.15 ; 4354,3023.15 4354.2,3033.61 ; 4354,3341.47 4354,3472.7 ; 4354,3341.47 4358.53,3341.47 ; 4354,3341.47 4354.2,3331.02 ; 4354,3472.7 4354,3603.94 ; 4354,3472.7 4358.53,3472.7 ; 4354,3603.94 4354,3735.17 ; 4354,3603.94 4358.53,3603.94 ; 4354,3735.17 4358.53,3735.17 ; 4354,3735.17 4354.34,3736.91 ; 4354.2,3033.61 4358.53,3023.15 ; 4354.2,3331.02 4358.53,3341.47 ; 4354.34,2627.71 4374.4,2579.3 ; 4354.34,2627.71 4358.53,2629.45 ; 4354.34,3736.91 4358.53,3735.17 ; 4354.34,3736.91 4374.4,3785.33 ; 4357.41,2529.9 4405.83,2509.85 ; 4357.41,2529.9 4359.15,2534.09 ; 4357.41,3834.72 4359.15,3830.53 ; 4357.41,3834.72 4405.83,3854.78 ; 4358.53,2629.45 4358.53,3023.15 ; 4358.53,2629.45 4358.79,2623.48 4359.57,2617.56 4360.86,2611.73 4362.66,2606.03 4364.94,2600.51 4367.7,2595.21 4370.91,2590.17 4374.55,2585.43 4378.59,2581.03 ; 4358.53,2629.45 4358.53,2760.68 ; 4358.53,2629.45 4378.59,2581.03 ; 4358.53,2760.68 4358.53,2891.92 ; 4358.53,2891.92 4358.53,3023.15 ; 4358.53,3341.47 4358.53,3735.17 ; 4358.53,3341.47 4358.53,3472.7 ; 4358.53,3472.7 4358.53,3603.94 ; 4358.53,3603.94 4358.53,3735.17 ; 4358.53,3735.17 4358.79,3741.14 4359.57,3747.06 4360.86,3752.89 4362.66,3758.59 4364.94,3764.11 4367.7,3769.41 4370.91,3774.45 4374.55,3779.19 4378.59,3783.59 ; 4358.53,3735.17 4378.59,3783.59 ; 4359.15,2534.09 4407.57,2514.04 ; 4359.15,2534.09 4376.85,2576.84 ; 4359.15,3830.53 4407.57,3850.59 ; 4359.15,3830.53 4376.85,3787.78 ; 4374.4,2579.3 4378.59,2581.03 ; 4374.4,2579.3 4376.85,2576.84 ; 4374.4,3785.33 4378.59,3783.59 ; 4374.4,3785.33 4376.85,3787.78 ; 4376.85,2576.84 4425.27,2556.78 ; 4376.85,2576.84 4378.59,2581.03 ; 4376.85,3787.78 4378.59,3783.59 ; 4376.85,3787.78 4425.27,3807.84 ; 4378.59,2581.03 4382.99,2577 4387.73,2573.36 4392.77,2570.15 4398.07,2567.39 4403.59,2565.1 4409.28,2563.31 4415.11,2562.02 4421.04,2561.24 4427.01,2560.97 ; 4378.59,2581.03 4427.01,2560.97 ; 4378.59,3783.59 4382.99,3787.63 4387.73,3791.26 4392.77,3794.47 4398.07,3797.23 4403.59,3799.52 4409.28,3801.32 4415.11,3802.61 4421.04,3803.39 4427.01,3803.65 ; 4378.59,3783.59 4427.01,3803.65 ; 4405.83,2509.85 4407.57,2514.04 ; 4405.83,2509.85 4416.55,2505.41 ; 4405.83,3854.78 4407.57,3850.59 ; 4405.83,3854.78 4416.55,3859.22 ; 4407.57,2514.04 4418.28,2509.59 ; 4407.57,2514.04 4425.27,2556.78 ; 4407.57,3850.59 4418.28,3855.03 ; 4407.57,3850.59 4425.27,3807.84 ; 4416.55,2505.41 4418.28,2509.59 ; 4416.55,2505.41 4427.01,2505.61 ; 4416.55,2505.41 4427.01,2501.07 ; 4416.55,3859.22 4418.28,3855.03 ; 4416.55,3859.22 4427.01,3863.55 ; 4416.55,3859.22 4427.01,3859.01 ; 4418.28,2509.59 4425.27,2556.78 ; 4418.28,2509.59 4427.01,2556.44 ; 4418.28,2509.59 4427.01,2505.61 ; 4418.28,3855.03 4427.01,3859.01 ; 4418.28,3855.03 4427.01,3808.18 ; 4418.28,3855.03 4425.27,3807.84 ; 4425.27,2556.78 4427.01,2560.97 ; 4425.27,2556.78 4427.01,2556.44 ; 4425.27,3807.84 4427.01,3803.65 ; 4425.27,3807.84 4427.01,3808.18 ; 4427.01,2501.07 4427.01,2560.97 ; 4427.01,2501.07 4623.86,2501.07 ; 4427.01,2501.07 4427.01,2560.97 ; 4427.01,2501.07 4427.01,2505.61 ; 4427.01,2501.07 4525.43,2501.07 ; 4427.01,2505.61 4525.43,2505.61 ; 4427.01,2505.61 4427.01,2556.44 ; 4427.01,2556.44 4427.01,2560.97 ; 4427.01,2556.44 4525.43,2556.44 ; 4427.01,2560.97 4623.86,2560.97 ; 4427.01,2560.97 4525.43,2560.97 ; 4427.01,3803.65 4623.86,3803.65 ; 4427.01,3803.65 4427.01,3863.55 ; 4427.01,3803.65 4427.01,3863.55 ; 4427.01,3803.65 4427.01,3808.18 ; 4427.01,3803.65 4525.43,3803.65 ; 4427.01,3808.18 4525.43,3808.18 ; 4427.01,3808.18 4427.01,3859.01 ; 4427.01,3859.01 4427.01,3863.55 ; 4427.01,3859.01 4525.43,3859.01 ; 4427.01,3863.55 4623.86,3863.55 ; 4427.01,3863.55 4525.43,3863.55 ; 4525.43,2501.07 4525.43,2505.61 ; 4525.43,2501.07 4623.86,2501.07 ; 4525.43,2505.61 4623.86,2505.61 ; 4525.43,2505.61 4525.43,2556.44 ; 4525.43,2556.44 4525.43,2560.97 ; 4525.43,2556.44 4623.86,2556.44 ; 4525.43,2560.97 4623.86,2560.97 ; 4525.43,3803.65 4525.43,3808.18 ; 4525.43,3803.65 4623.86,3803.65 ; 4525.43,3808.18 4623.86,3808.18 ; 4525.43,3808.18 4525.43,3859.01 ; 4525.43,3859.01 4525.43,3863.55 ; 4525.43,3859.01 4623.86,3859.01 ; 4525.43,3863.55 4623.86,3863.55 ; 4623.86,2501.07 4623.86,2560.97 ; 4623.86,2501.07 4623.86,2505.61 ; 4623.86,2505.61 4623.86,2556.44 ; 4623.86,2556.44 4623.86,2560.97 ; 4623.86,3803.65 4623.86,3863.55 ; 4623.86,3803.65 4623.86,3808.18 ; 4623.86,3808.18 4623.86,3859.01 ; 4623.86,3859.01 4623.86,3863.55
